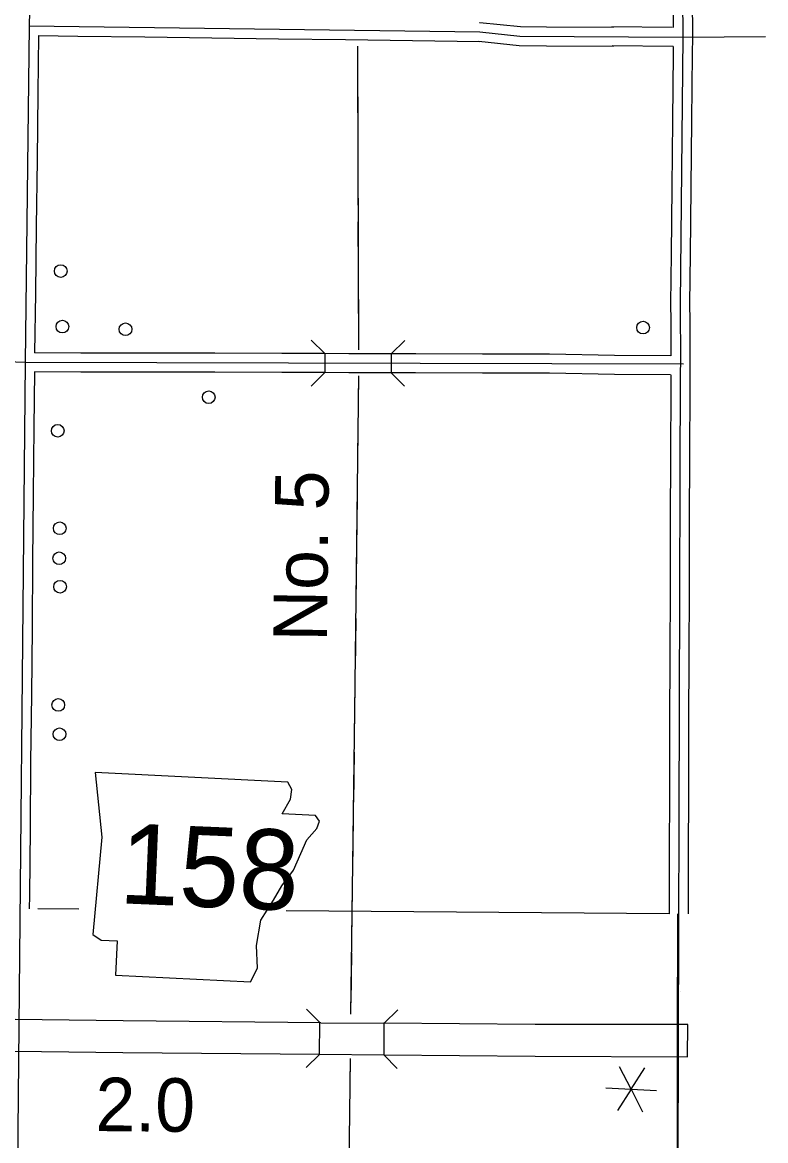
# Model space of a CAD drawing. Extents: x -4306 to 3843, y 131 to 8053.
# Drawn here: x 1443 to 2381, y 3441 to 4853 of the extents above; entities that cross this region are included whole.
import ezdxf

# ---------------------------------------------------------------- set-up
doc = ezdxf.new("R2010")
doc.units = 0
for name, color, linetype in [('10', 7, 'Continuous'), ('21', 7, 'Continuous'), ('32', 7, 'Continuous'), ('34', 7, 'Continuous'), ('37', 7, 'Continuous'), ('38', 7, 'Continuous'), ('43', 7, 'Continuous'), ('48', 7, 'Continuous'), ('56', 7, 'Continuous'), ('6', 7, 'Continuous')]:
    doc.layers.add(name, color=color, linetype=linetype)

msp = doc.modelspace()

# ---------------------------------------------------------------- linework, layer by layer
at = {"layer": '10'}
for p, q in [((1818.2, 3549.7), (1818.5, 3589.8)), ((1819.6, 3589.7), (1899.4, 3589)), ((1899.4, 3589), (1899.4, 3549)), ((2282.6, 3546.7), (2282.9, 3587.4)), ((1817.9, 3549.8), (1899.4, 3549))]:
    msp.add_line(p, q, dxfattribs=at)
for points in [[(1819.6, 3589.7), (1570.2, 3591.9), (1399.5, 3594.1), (1244.5, 3599.9)], [(2282.9, 3587.4), (2090.3, 3587.4), (1899.4, 3589)], [(1243, 3559.9), (1398.5, 3554.1), (1569.7, 3551.9), (1817.9, 3549.8)], [(1899.4, 3549), (2090.1, 3547.4), (2282.6, 3546.7)]]:
    msp.add_lwpolyline(points, dxfattribs=at)
at = {"layer": '21'}
msp.add_lwpolyline([(1535, 3905.7), (1543.2, 3824), (1531.8, 3701.2), (1542.3, 3693.9), (1562.6, 3693), (1560.5, 3649.7), (1730.8, 3641.4), (1739.8, 3658.5), (1738.5, 3687.1), (1744.1, 3719.3), (1760.2, 3744.3), (1770.6, 3762.7), (1785.1, 3782.4), (1794.3, 3803.6), (1801.9, 3820.8), (1814.8, 3835.1), (1818, 3844.4), (1812.9, 3851.5), (1771, 3853.5), (1781.4, 3872), (1783.3, 3884.1), (1778.2, 3893.7)], close=True, dxfattribs=at)
at = {"layer": '32'}
for p, q in [((1457.4, 5294.3), (1451.8, 4848.8)), ((2273.4, 5266), (2276.7, 4834.6)), ((2273.4, 5266), (2276.7, 4834.6)), ((2264.2, 4898.1), (2264.6, 4846.6)), ((2288.2, 4898.3), (2288.7, 4834.6)), ((1451.8, 4848.8), (1446.4, 4423.8)), ((1451.8, 4848.8), (2020.4, 4841.2)), ((2020.2, 4853.2), (2020.5, 4853.2)), ((2020.5, 4853.2), (2071.6, 4848)), ((2071.6, 4848), (2104.7, 4847.8)), ((2104.7, 4847.8), (2189.2, 4847.2)), ((2263.1, 4846.9), (2187.1, 4847.4)), ((1463.6, 4836.6), (1462.7, 4764.1)), ((1463.6, 4836.6), (1513, 4835.9)), ((1513, 4835.9), (1597.5, 4834.8)), ((1597.5, 4834.8), (1682, 4833.7)), ((1682, 4833.7), (1766.4, 4832.6)), ((1766.4, 4832.6), (1850.9, 4831.5)), ((1850.9, 4831.5), (1935.4, 4830.4)), ((2020.4, 4841.2), (2070.9, 4836)), ((2070.9, 4836), (2276.7, 4834.5)), ((2276.7, 4834.6), (2273.1, 4498.1)), ((2276.7, 4834.6), (2273.1, 4498.1)), ((2276.7, 4834.6), (2381.1, 4835.3)), ((2288.7, 4834.6), (2288.5, 4813.6)), ((1935.4, 4830.4), (2019.9, 4829.2)), ((2019.1, 4829.3), (2070.2, 4824)), ((2019.9, 4829.2), (2020.2, 4829.2)), ((2070.2, 4824), (2104.5, 4823.8)), ((2104.5, 4823.8), (2189, 4823.2)), ((2264.6, 4822.8), (2187.3, 4823.4)), ((2264.6, 4822.6), (2264.5, 4813.8)), ((2264.5, 4813.8), (2263.6, 4729.3)), ((2288.5, 4813.6), (2287.6, 4729.1)), ((1462.7, 4764.1), (1461.6, 4679.6)), ((2263.6, 4729.3), (2262.7, 4644.9)), ((2287.6, 4729.1), (2286.7, 4644.6)), ((1461.6, 4679.6), (1460.5, 4595.2)), ((2262.7, 4644.9), (2261.8, 4560.4)), ((2286.7, 4644.6), (2285.8, 4560.1)), ((1460.5, 4595.2), (1459.5, 4510.7)), ((2261.8, 4560.4), (2261.1, 4498.1)), ((2285.8, 4560.1), (2285.1, 4498.1)), ((1459.5, 4510.7), (1458.5, 4435.8)), ((2261.1, 4498.1), (2261.3, 4475.7)), ((2273.1, 4498.1), (2273.7, 4420.5)), ((2273.1, 4498.1), (2273.7, 4420.5)), ((2285.1, 4498.1), (2285.3, 4475.8)), ((2261.3, 4475.7), (2261.6, 4432)), ((2285.3, 4475.8), (2285.7, 4420.3)), ((1517, 4435.6), (1458.5, 4435.8)), ((1601.5, 4435.4), (1517, 4435.6)), ((1686, 4435.2), (1601.5, 4435.4)), ((1446.4, 4423.8), (1130.8, 4433)), ((1446.4, 4423.8), (1434.2, 3147)), ((2277.4, 4421.6), (1446.4, 4423.8)), ((1770.5, 4434.9), (1686, 4435.2)), ((1824.7, 4434.8), (1770.5, 4434.9)), ((1824.7, 4434.8), (1824.7, 4410.8)), ((1855, 4434.7), (1824.7, 4434.8)), ((1908.7, 4434.6), (1855, 4434.7)), ((1908.7, 4434.6), (1908.6, 4410.6)), ((1939.5, 4434.5), (1908.7, 4434.6)), ((2024, 4434.3), (1939.5, 4434.5)), ((2108.4, 4434), (2024, 4434.3)), ((2190.3, 4432.3), (2108.4, 4434)), ((2261.6, 4432), (2190.3, 4432.3)), ((1458.2, 4411.8), (1457.6, 4341.7)), ((1517, 4411.6), (1458.2, 4411.8)), ((1601.4, 4411.4), (1517, 4411.6)), ((1685.9, 4411.2), (1601.4, 4411.4)), ((1770.4, 4410.9), (1685.9, 4411.2)), ((1824.6, 4410.8), (1770.4, 4410.9)), ((1854.9, 4410.7), (1824.6, 4410.8)), ((1908.6, 4410.6), (1854.9, 4410.7)), ((1939.4, 4410.5), (1908.6, 4410.6)), ((2023.9, 4410.3), (1939.4, 4410.5)), ((2108.4, 4410), (2023.9, 4410.3)), ((2190.2, 4408.3), (2108.4, 4410)), ((2261.1, 4408), (2190.2, 4408.3)), ((2261.3, 4408), (2261.3, 4391.3)), ((2273.4, 4414.4), (2270.8, 3567.2)), ((2273.4, 4414.4), (2270.8, 3567.2)), ((2273.7, 4420.5), (2273.4, 4414.4)), ((2273.7, 4420.5), (2273.4, 4414.4)), ((2285.4, 4414.1), (2285.3, 4391.2)), ((2285.7, 4420.3), (2285.4, 4414.1)), ((2261.3, 4391.3), (2261, 4306.8)), ((2285.3, 4391.2), (2285, 4306.8)), ((1457.6, 4341.7), (1456.8, 4257.3)), ((2261, 4306.8), (2260.8, 4222.3)), ((2285, 4306.8), (2284.8, 4222.3)), ((1456.8, 4257.3), (1456, 4172.8)), ((2260.8, 4222.3), (2260.5, 4137.8)), ((2284.8, 4222.3), (2284.5, 4137.8)), ((1456, 4172.8), (1455.2, 4088.3)), ((2260.5, 4137.8), (2260.3, 4053.4)), ((2284.5, 4137.8), (2284.3, 4053.3)), ((1455.2, 4088.3), (1454.4, 4003.8)), ((2260.3, 4053.4), (2260, 3968.9)), ((2284.3, 4053.3), (2284, 3968.8)), ((1454.4, 4003.8), (1453.5, 3919.3)), ((2260, 3968.9), (2259.8, 3884.4)), ((2284, 3968.8), (2283.8, 3884.3)), ((1453.5, 3919.3), (1452.7, 3834.8)), ((2259.8, 3884.4), (2259.5, 3799.9)), ((2283.8, 3884.3), (2283.5, 3799.8)), ((1452.7, 3834.8), (1451.9, 3750.3)), ((2259.5, 3799.9), (2259.3, 3727.1)), ((2283.5, 3799.8), (2283.3, 3727.1)), ((1451.9, 3750.3), (1451.8, 3733.5)), ((2270.8, 3567.2), (2270, 3142.7)), ((2270.8, 3567.2), (2270, 3142.7))]:
    msp.add_line(p, q, dxfattribs=at)
at = {"layer": '34'}
for p, q in [((2270.1, 3568.1), (2270.4, 3727.2)), ((2269.9, 3407.2), (2270.1, 3568.1))]:
    msp.add_line(p, q, dxfattribs=at)
at = {"layer": '37'}
for p, q in [((1818.4, 3569.7), (1818.4, 3569.7)), ((1899.6, 3569), (1899.6, 3569))]:
    msp.add_line(p, q, dxfattribs=at)
for points in [[(1818.5, 3589.8), (1801.7, 3606.9)], [(1916.9, 3605.9), (1899.7, 3589)], [(1801.1, 3532.9), (1818.2, 3549.7)], [(1899.4, 3549), (1916.2, 3531.9)]]:
    msp.add_lwpolyline(points, dxfattribs=at)
at = {"layer": '38'}
for points in [[(1807.7, 4451.8), (1824.7, 4434.8)], [(1908.7, 4434.6), (1925.7, 4451.5)], [(1824.6, 4410.8), (1807.6, 4393.9)], [(1925.5, 4393.6), (1908.6, 4410.6)]]:
    msp.add_lwpolyline(points, dxfattribs=at)
at = {"layer": '43'}
for points in [[(1865.9, 4823.2), (1867.2, 4439.7)], [(1865.9, 4823.2), (1866, 4791.5)], [(1866.1, 4770.4), (1866.3, 4707)], [(1866.3, 4685.9), (1866.6, 4622.5)], [(1866.6, 4601.4), (1866.9, 4538.1)], [(1866.9, 4516.9), (1867.1, 4453.6)], [(1867.2, 4406.7), (1862.4, 3983.1), (1858.9, 3726.4), (1857.4, 3600.4)], [(1867.2, 4406.7), (1866.9, 4375)], [(1866.6, 4353.9), (1865.9, 4290.5)], [(1865.7, 4269.4), (1865, 4206)], [(1864.7, 4184.9), (1864, 4121.5)], [(1863.8, 4100.4), (1863, 4037)], [(1862.8, 4015.9), (1862.4, 3983.1), (1862, 3952.6)], [(1861.7, 3931.4), (1861.3, 3899.8)], [(1861.3, 3899.8), (1860.9, 3868.1)], [(1860.6, 3847), (1859.7, 3783.6)], [(1859.4, 3762.5), (1858.9, 3726.4), (1858.6, 3699.1)], [(1858.3, 3678), (1857.6, 3614.6)], [(1856.7, 3544.3), (1855.1, 3408.4), (1855.5, 3288.6), (1853.4, 3161.1)], [(1856.7, 3544.3), (1856.4, 3512.6)], [(1856.1, 3491.5), (1855.4, 3428.1)]]:
    msp.add_lwpolyline(points, dxfattribs=at)
at = {"layer": '48'}
for p, q in [((2211.3, 3505.7), (2196.7, 3534.1)), ((2211.3, 3505.7), (2228.6, 3532.6)), ((2179.3, 3507.2), (2211.3, 3505.7)), ((2211.3, 3505.7), (2194, 3478.8)), ((2211.3, 3505.7), (2243.3, 3504.1)), ((2211.3, 3505.7), (2225.9, 3477.2))]:
    msp.add_line(p, q, dxfattribs=at)
at = {"layer": '56'}
for centre in [(1491.5, 4539.1), (1493.5, 4469), (1573.2, 4465.6), (2226.5, 4467.7), (1678.2, 4379.8), (1487.7, 4337.3), (1490.3, 4214.3), (1489.5, 4176.3), (1490.6, 4140.3), (1488.4, 3991), (1489.9, 3954.1)]:
    msp.add_circle(centre, 8, dxfattribs=at)
at = {"layer": '6'}
for points in [[(1514.1, 3733.1), (1462.5, 3733.5)], [(2259.3, 3727.3), (1776.1, 3731)]]:
    msp.add_lwpolyline(points, dxfattribs=at)
msp.add_lwpolyline([(2274.2, 3629.7), (2274.2, 3629.7), (2274.2, 3629.7)], close=True, dxfattribs=at)

# ---------------------------------------------------------------- texts
at = {"layer": '21'}
msp.add_text('158', height=101.29, rotation=357.6004, dxfattribs=at).set_placement((1564.3, 3740.6))
at = {"layer": '43'}
msp.add_text('No. 5', height=67.59, rotation=89.3217, dxfattribs=at).set_placement((1827.3, 4070.8))
at = {"layer": '48'}
msp.add_text('2.0', height=67.59, rotation=359.5003, dxfattribs=at).set_placement((1535.1, 3452.8))

doc.saveas('drawing.dxf')
